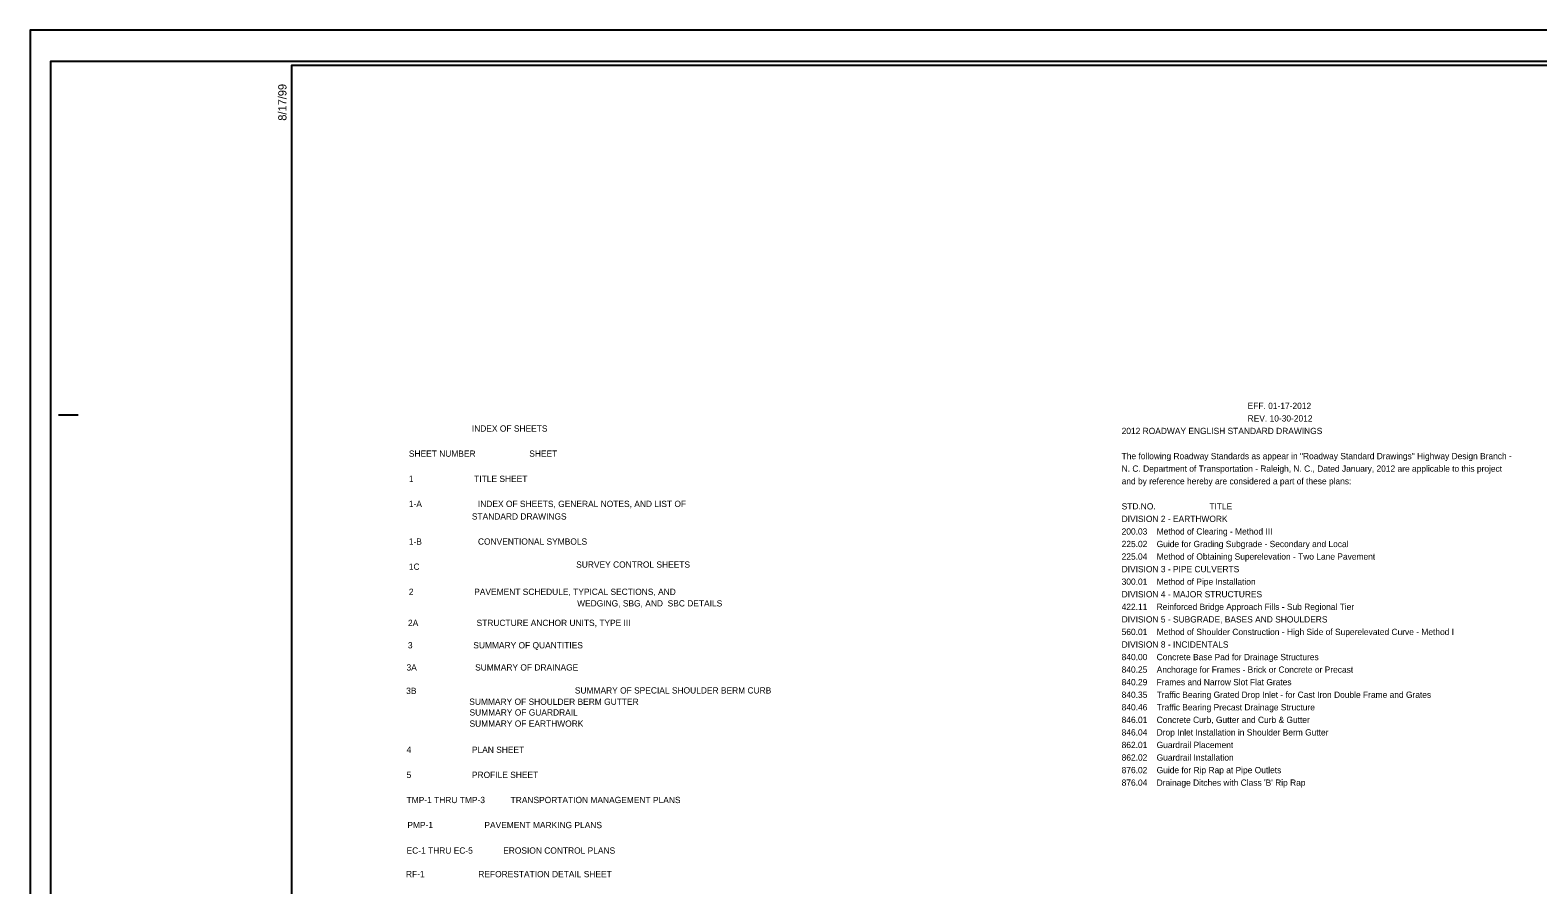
# Model space of a CAD drawing. Extents: x 573844.3 to 573878, y -53348.9 to -53327.
# Drawn here: x 573844.29 to 573863.49, y -53337.92 to -53327.03 of the extents above; entities that cross this region are included whole.
import ezdxf

# ---------------------------------------------------------------- set-up
doc = ezdxf.new("R2010")
doc.units = 0
for name, color, linetype in [('Default', 7, 'Continuous'), ('Prop Dimension Text', 7, 'Continuous'), ('Sheet Cutting Line CELL', 7, 'Continuous'), ('Sheet Plan CELL', 7, 'Continuous'), ('Sheet Plot Border Inside CELL', 7, 'Continuous'), ('Sheet Plot Border Outside CELL', 7, 'Continuous')]:
    doc.layers.add(name, color=color, linetype=linetype)

msp = doc.modelspace()

# ---------------------------------------------------------------- linework, layer by layer
at = {"layer": 'Sheet Cutting Line CELL'}
for p, q in [((573877.959, -53327.032), (573844.289, -53327.032)), ((573844.289, -53327.032), (573844.289, -53348.932))]:
    msp.add_line(p, q, dxfattribs=at)
at = {"layer": 'Sheet Plan CELL'}
for p, q in [((573847.619, -53327.482), (573847.619, -53327.482)), ((573844.649, -53331.932), (573844.899, -53331.932))]:
    msp.add_line(p, q, dxfattribs=at)
msp.add_lwpolyline([(573877.619, -53327.482), (573847.619, -53327.482), (573847.619, -53348.482), (573877.619, -53348.482)], close=True, dxfattribs=at)
at = {"layer": 'Sheet Plot Border Inside CELL'}
msp.add_lwpolyline([(573844.549, -53348.532), (573877.869, -53348.532), (573877.869, -53327.432), (573844.549, -53327.432)], close=True, dxfattribs=at)
at = {"layer": 'Sheet Plot Border Outside CELL'}
msp.add_lwpolyline([(573844.289, -53348.932), (573877.959, -53348.932), (573877.959, -53327.032), (573844.289, -53327.032)], close=True, dxfattribs=at)

# ---------------------------------------------------------------- texts
at = {"layer": 'Default'}
for s, p in [('                                                      EFF. 01-17-2012', (573858.192, -53331.858)), ('2012 ROADWAY ENGLISH STANDARD DRAWINGS', (573858.192, -53332.178)), ('                                                      REV. 10-30-2012', (573858.192, -53332.018)), ('The following Roadway Standards as appear in "Roadway Standard Drawings" Highway Design Branch -', (573858.192, -53332.498)), ('N. C. Department of Transportation - Raleigh, N. C., Dated January, 2012 are applicable to this project', (573858.192, -53332.658)), ('and by reference hereby are considered a part of these plans:', (573858.192, -53332.818)), ('STD.NO.                       TITLE', (573858.192, -53333.138)), ('DIVISION 2 - EARTHWORK', (573858.192, -53333.298)), ('200.03    Method of Clearing - Method III', (573858.192, -53333.458)), ('225.02    Guide for Grading Subgrade - Secondary and Local', (573858.192, -53333.618)), ('225.04    Method of Obtaining Superelevation - Two Lane Pavement', (573858.192, -53333.778)), ('300.01    Method of Pipe Installation ', (573858.192, -53334.098)), ('DIVISION 3 - PIPE CULVERTS', (573858.192, -53333.938)), ('DIVISION 4 - MAJOR STRUCTURES', (573858.192, -53334.258)), ('422.11    Reinforced Bridge Approach Fills - Sub Regional Tier', (573858.192, -53334.418)), ('DIVISION 5 - SUBGRADE, BASES AND SHOULDERS', (573858.192, -53334.578)), ('560.01    Method of Shoulder Construction - High Side of Superelevated Curve - Method I', (573858.192, -53334.738)), ('840.00    Concrete Base Pad for Drainage Structures', (573858.192, -53335.058)), ('DIVISION 8 - INCIDENTALS', (573858.192, -53334.898)), ('840.25    Anchorage for Frames - Brick or Concrete or Precast', (573858.192, -53335.218)), ('840.29    Frames and Narrow Slot Flat Grates', (573858.192, -53335.378)), ('840.35    Traffic Bearing Grated Drop Inlet - for Cast Iron Double Frame and Grates', (573858.192, -53335.538)), ('840.46    Traffic Bearing Precast Drainage Structure', (573858.192, -53335.698)), ('846.01    Concrete Curb, Gutter and Curb & Gutter', (573858.192, -53335.858)), ('846.04    Drop Inlet Installation in Shoulder Berm Gutter', (573858.192, -53336.018)), ('862.01    Guardrail Placement', (573858.192, -53336.178)), ('862.02    Guardrail Installation', (573858.192, -53336.338)), ('876.02    Guide for Rip Rap at Pipe Outlets', (573858.192, -53336.498)), ("876.04    Drainage Ditches with Class 'B' Rip Rap", (573858.192, -53336.658))]:
    msp.add_text(s, height=0.08, dxfattribs=at).set_placement(p)
at = {"layer": 'Prop Dimension Text'}
for s, p in [('                           INDEX OF SHEETS ', (573849.113, -53332.147)), ('SHEET NUMBER                       SHEET   ', (573849.113, -53332.467)), ('1                          TITLE SHEET', (573849.113, -53332.787)), ('1-A                        INDEX OF SHEETS, GENERAL NOTES, AND LIST OF ', (573849.113, -53333.107)), ('                           STANDARD DRAWINGS', (573849.113, -53333.267)), ('1-B                        CONVENTIONAL SYMBOLS ', (573849.113, -53333.587)), ('1C', (573849.113, -53333.907)), ('SURVEY CONTROL SHEETS', (573851.244, -53333.88)), ('2                          PAVEMENT SCHEDULE, TYPICAL SECTIONS, AND ', (573849.113, -53334.227)), ('WEDGING, SBG, AND  SBC DETAILS', (573851.256, -53334.374)), ('2A                         STRUCTURE ANCHOR UNITS, TYPE III', (573849.102, -53334.623)), ('3                          SUMMARY OF QUANTITIES ', (573849.101, -53334.908)), ('3A                         SUMMARY OF DRAINAGE', (573849.083, -53335.19)), ('3B', (573849.079, -53335.488)), ('                           SUMMARY OF SHOULDER BERM GUTTER', (573849.08, -53335.627)), ('SUMMARY OF SPECIAL SHOULDER BERM CURB', (573851.227, -53335.483)), ('                           SUMMARY OF GUARDRAIL', (573849.083, -53335.764)), ('                           SUMMARY OF EARTHWORK', (573849.083, -53335.906)), ('4                          PLAN SHEET', (573849.084, -53336.239)), ('5                          PROFILE SHEET  ', (573849.084, -53336.559)), ('TMP-1 THRU TMP-3           TRANSPORTATION MANAGEMENT PLANS', (573849.084, -53336.879)), ('PMP-1                      PAVEMENT MARKING PLANS', (573849.094, -53337.198)), ('EC-1 THRU EC-5             EROSION CONTROL PLANS', (573849.084, -53337.523)), ('RF-1                       REFORESTATION DETAIL SHEET', (573849.076, -53337.823))]:
    msp.add_text(s, height=0.08, dxfattribs=at).set_placement(p)
at = {"layer": 'Sheet Plan CELL'}
msp.add_text('8/17/99', height=0.105, rotation=90, dxfattribs=at).set_placement((573847.554, -53328.186))

doc.saveas('drawing.dxf')
